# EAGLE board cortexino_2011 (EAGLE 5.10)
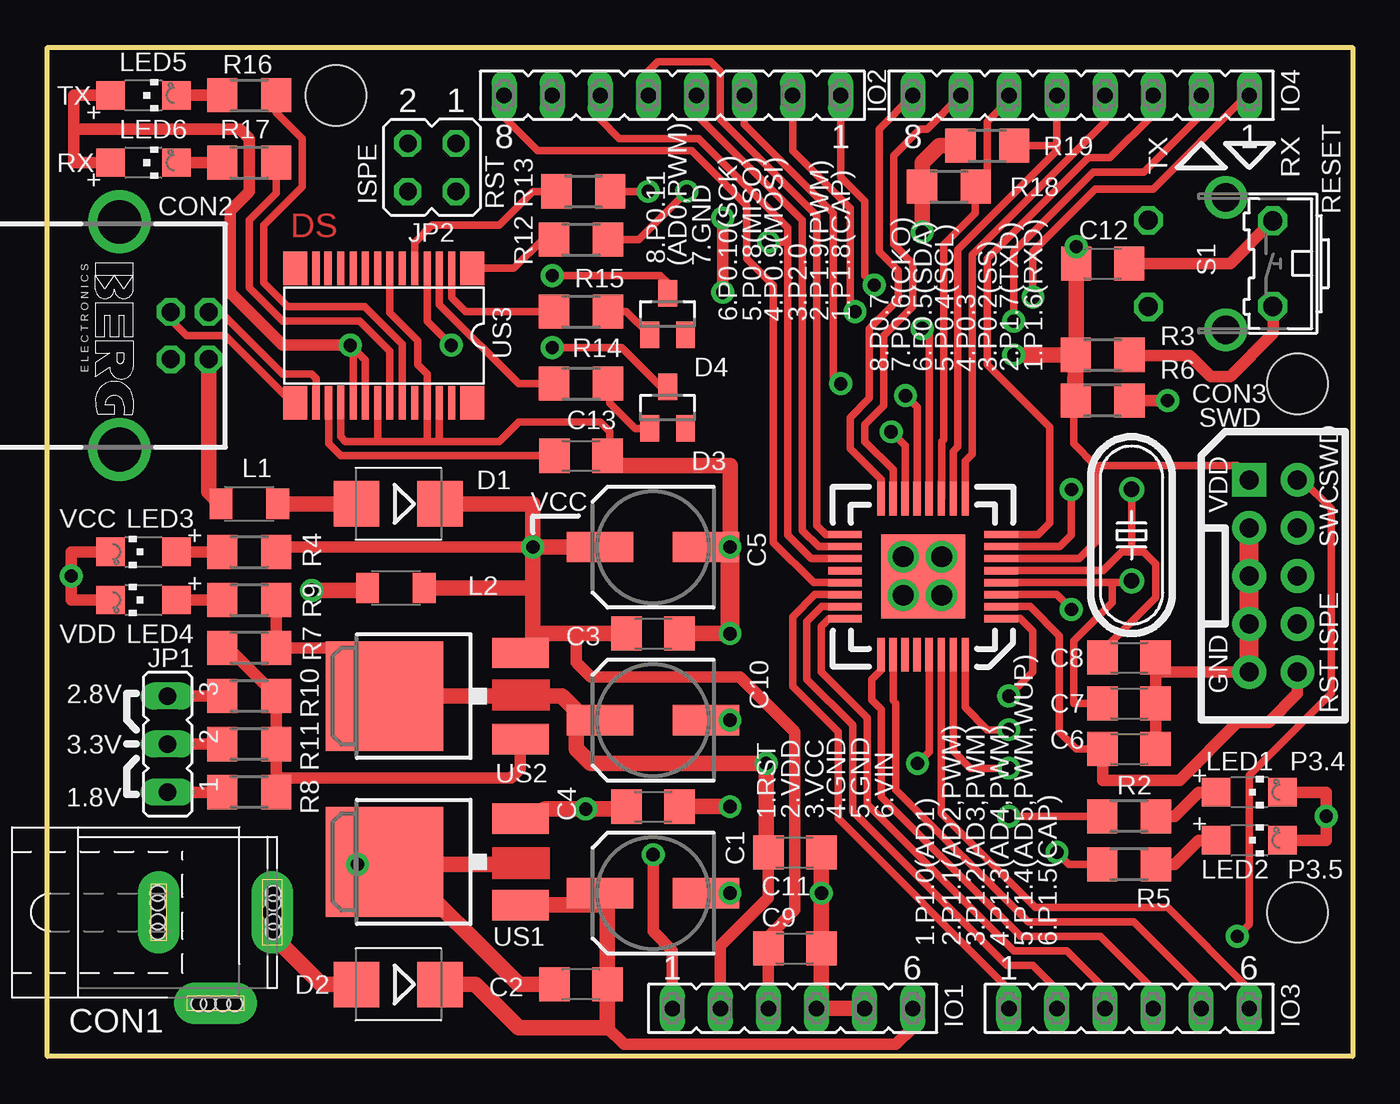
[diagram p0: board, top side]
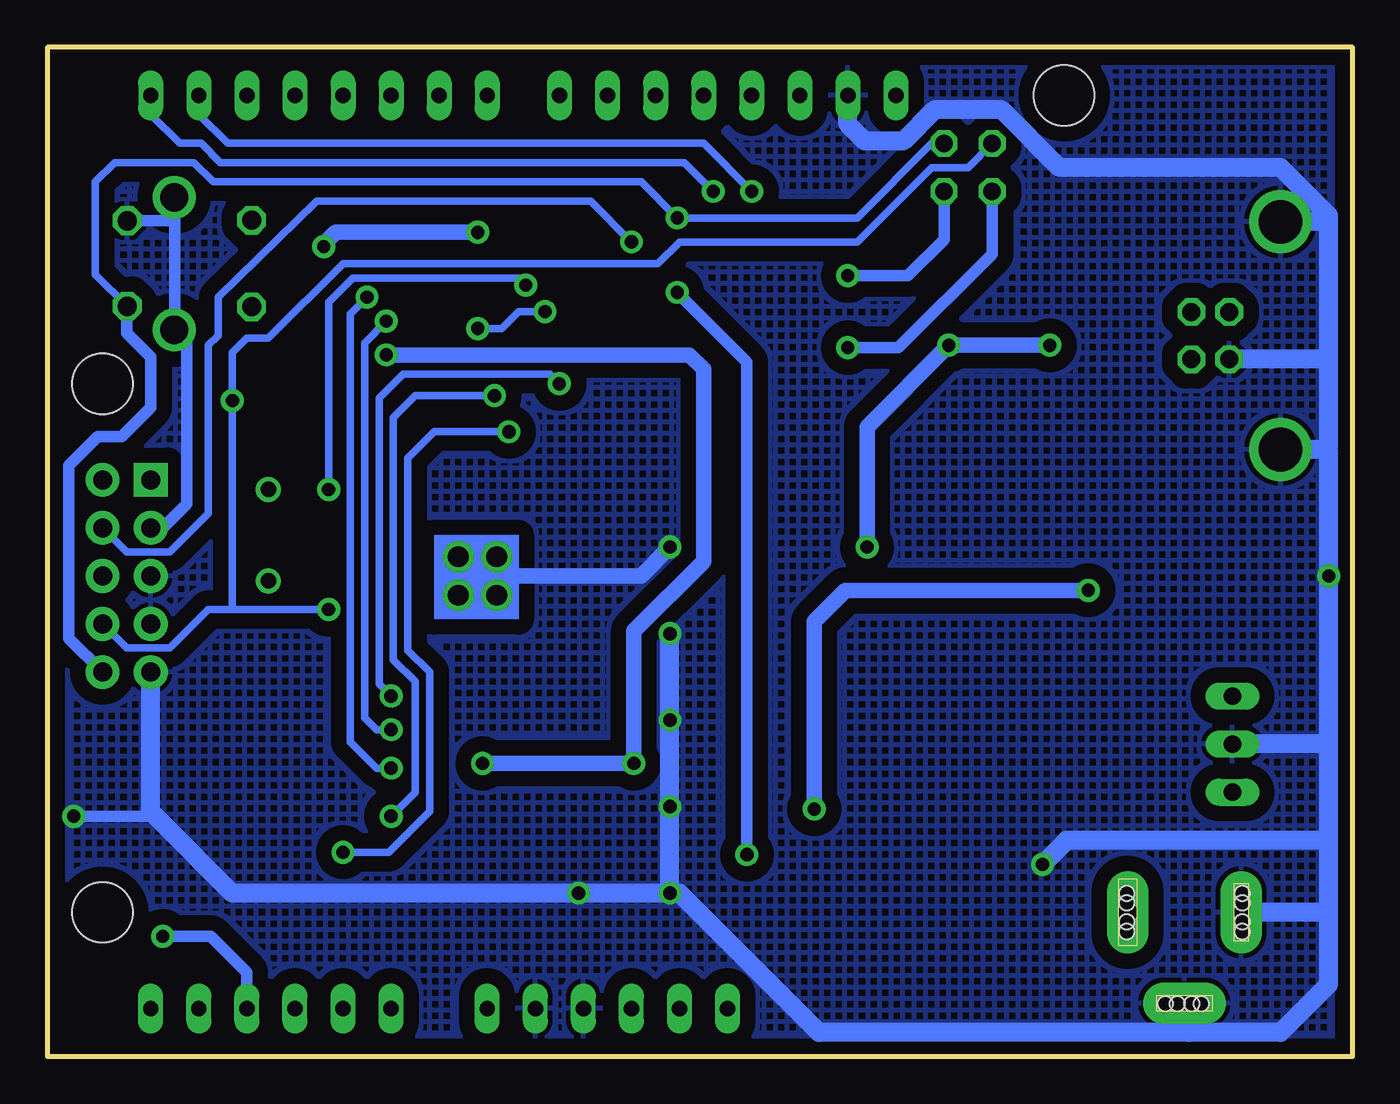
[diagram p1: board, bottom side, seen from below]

Size 68.96 x 53.34 mm. Coordinates in mm from the lower left corner, seen from the top.
Outline: 0,53.34 68.96,53.34 68.96,0 0,0 0,53.34
Copper layers (1*16): Top 0.035mm / dielectric 1.5mm / Bottom 0.035mm
Design rules "default *": minimum track width 6mil, minimum drill 12mil, track to track 6mil, track to pad 6mil, pad to pad 6mil, via to via 6mil, smd to smd 6mil, copper to edge 30mil, drill to drill 6mil, minimum pad ring 10mil, minimum via ring 10mil, stop-mask expansion 4mil, vias tented up to drill 0mil, thermal gap 10mil
Net classes: 0 default: width 0.254 mm, drill 0.305 mm, clearance 0.152 mm; 1 power: width 0.61 mm, drill 0.508 mm, clearance 0.152 mm; 2 gnd: width 0.305 mm, drill 0.508 mm, clearance 0.152 mm; 3 usbvcc: width 0.508 mm, drill 0.508 mm, clearance 0.152 mm; 4 aref: width 0.406 mm
Holes 3.2 mm at 66.04,35.56 66.04,7.62 15.24,50.8
Holes 0.8 mm at 5.84,7.11 5.84,6.6 5.84,8.13 5.84,8.64 8.51,2.79 9.27,2.79 8,2.79 9.91,2.79 11.94,8.13 11.94,8.64 11.94,7.11 11.94,6.6

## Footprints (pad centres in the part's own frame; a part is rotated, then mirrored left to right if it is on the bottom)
SANYO-OSCON_SMD_C6 = smd 3.5 x 1.6: + 2.8,0; - -2.8,0
C1206 = smd 1.6 x 1.8: 1 -1.4,0; 2 1.4,0
SPC4077 = drill 0.8 pad 2.184 long: 1 -3,0; 2 0,-4.8 | drill 1 pad 2.184 long: 3 3,0
PN61729-S = drill 0.95 octagon: 1 1.25,4.71; 2 -1.25,4.71; 3 -1.25,2.71; 4 1.25,2.71 | drill 2.3 pad 2.9 round: S1 -6.02,0; S2 6.02,0
CON10 = drill 1 pad 1.778 square: 1 -1.27,5.08 | drill 1 pad 1.778 round: 2 1.27,5.08; 3 -1.27,2.54; 4 1.27,2.54; 5 -1.27,0; 6 1.27,0; 7 -1.27,-2.54; 8 1.27,-2.54; 9 -1.27,-5.08; 10 1.27,-5.08
SMB = smd 2.4 x 2.4: A 2.2,0; C -2.2,0
SOT23 = smd 1 x 1.4: 1 -0.95,-1.1; 2 0.95,-1.1; 3 0,1.1
FE06 = drill 0.813 long: 1 -6.35,0; 2 -3.81,0; 3 -1.27,0; 4 1.27,0; 5 3.81,0; 6 6.35,0
FE08 = drill 0.813 long: 1 -8.89,0; 2 -6.35,0; 3 -3.81,0; 4 -1.27,0; 5 1.27,0; 6 3.81,0; 7 6.35,0; 8 8.89,0
JP2 = drill 0.914 long: 1 -2.54,0; 2 0,0; 3 2.54,0
JP2Q = drill 0.914 octagon: 1 -1.27,-1.27; 2 -1.27,1.27; 3 1.27,-1.27; 4 1.27,1.27
L3216C = smd 1.2 x 1.6: 1 -1.5,0; 2 1.5,0
CHIPLED_1206 = smd 1.5 x 1.5: A 0,-1.75; C 0,1.75
HC49/S = drill 0.813 round: 1 -2.413,0; 2 2.413,0
R1206 = smd 1.6 x 1.803: 1 -1.422,0; 2 1.422,0
B3F-31XX = drill 1.016 octagon: 1 -2.261,-1.245; 2 2.261,-1.245 | drill 1.499 pad 2.159 round: 3 -3.505,1.245; 4 3.505,1.245
DPACK = smd 1.6 x 3: 1 -2.28,-4.8; 3 2.28,-4.8 | smd 5.8 x 6.2: 4 0,2.38
TSSOP28 = smd 1.27 x 1.778: 1 -4.674,-3.556; 14 4.674,-3.556; 15 4.674,3.556; 28 -4.674,3.556 | smd 0.381 x 1.778: 2 -3.581,-3.556; 3 -2.921,-3.556; 4 -2.286,-3.556; 5 -1.626,-3.556; 6 -0.965,-3.556; 7 -0.305,-3.556; 8 0.33,-3.556; 9 0.991,-3.556; 10 1.626,-3.556; 11 2.286,-3.556; 12 2.946,-3.556; 13 3.581,-3.556; 16 3.581,3.556; 17 2.921,3.556; 18 2.286,3.531; 19 1.626,3.556; 20 0.991,3.556; 21 0.33,3.556; 22 -0.305,3.556; 23 -0.965,3.556; 24 -1.626,3.556; 25 -2.286,3.556; 26 -2.921,3.556; 27 -3.581,3.556
HVQFN33 = smd 0.381 x 1.778: 1 -2.54,-3.81; 2 -1.905,-3.81; 3 -1.27,-3.81; 4 -0.635,-3.81; 5 0,-3.81; 6 0.635,-3.81; 7 1.27,-3.81; 8 1.905,-3.81; 17 1.905,4.445; 18 1.27,4.445; 19 0.635,4.445; 20 0,4.445; 21 -0.635,4.445; 22 -1.27,4.445; 23 -1.905,4.445; 24 -2.54,4.445 | smd 1.778 x 0.381: 9 3.81,-1.905; 10 3.81,-1.27; 11 3.81,-0.635; 12 3.81,0; 13 3.81,0.635; 14 3.81,1.27; 15 3.81,1.905; 16 3.81,2.54; 25 -4.445,2.54; 26 -4.445,1.905; 27 -4.445,1.27; 28 -4.445,0.635; 29 -4.445,0; 30 -4.445,-0.635; 31 -4.445,-1.27; 32 -4.445,-1.905 | smd 4.445 x 4.445: 33 -0.318,0.318

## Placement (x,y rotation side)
C1  100u  [SANYO-OSCON_SMD_C6]  32,8.64 180 top
C2  100n  [C1206]  28.19,3.81 180 top
C3  100u  [SANYO-OSCON_SMD_C6]  32,26.92 180 top
C4  100n  [C1206]  32,13.21 0 top
C5  100n  [C1206]  32,22.35 0 top
C6  100n  [C1206]  57.15,16.26 0 top
C7  18p  [C1206]  57.15,18.67 0 top
C8  18p  [C1206]  57.15,21.08 0 top
C9  100n  [C1206]  39.5,5.71 0 top
C10  100u  [SANYO-OSCON_SMD_C6]  32,17.78 180 top
C11  100n  [C1206]  39.5,10.79 0 top
C12  100n  [C1206]  55.75,41.91 0 top
C13  100n  [C1206]  28.19,31.75 0 top
CON1  [SPC4077]  8.89,7.62 0 top
CON2  [PN61729-S]  3.81,38.1 270 top
CON3  [CON10]  64.77,25.4 0 top
D1  BAS85  [SMB]  18.54,29.21 180 top
D2  4007  [SMB]  18.54,3.81 180 top
D3  [SOT23]  32.77,34.29 0 top
D4  [SOT23]  32.77,39.24 0 top
IO1  [FE06]  39.37,2.54 0 top
IO2  [FE08]  33.02,50.8 180 top
IO3  [FE06]  57.15,2.54 0 top
IO4  [FE08]  54.61,50.8 180 top
JP1  [JP2]  6.35,16.51 90 top
JP2  [JP2Q]  20.32,46.99 180 top
L1  1uH  [L3216C]  10.67,29.21 0 top
L2  1uH  [L3216C]  18.41,24.77 0 top
LED1  [CHIPLED_1206]  63.5,13.97 270 top
LED2  [CHIPLED_1206]  63.5,11.43 270 top
LED3  [CHIPLED_1206]  5.08,26.67 90 top
LED4  [CHIPLED_1206]  5.08,24.13 90 top
LED5  [CHIPLED_1206]  5.08,50.8 270 top
LED6  [CHIPLED_1206]  5.08,47.24 270 top
Q1  12MHz  [HC49/S]  57.28,27.56 270 top
R2  1k  [R1206]  57.15,12.7 0 top
R3  10k  [R1206]  55.75,37.08 180 top
R4  1k  [R1206]  10.67,26.67 180 top
R5  1k  [R1206]  57.15,10.16 0 top
R6  10k  [R1206]  55.75,34.67 0 top
R7  330R  [R1206]  10.67,21.59 0 top
R8  10R  [R1206]  10.67,13.97 0 top
R9  1k  [R1206]  10.67,24.13 180 top
R10  220R  [R1206]  10.67,19.05 0 top
R11  150R  [R1206]  10.67,16.51 0 top
R12  1k  [R1206]  28.19,43.18 180 top
R13  1k  [R1206]  28.32,45.72 180 top
R14  1k  [R1206]  28.19,35.56 180 top
R15  1k  [R1206]  28.19,39.37 180 top
R16  1k  [R1206]  10.67,50.8 180 top
R17  1k  [R1206]  10.67,47.24 180 top
R18  4k7  [R1206]  47.62,45.97 180 top
R19  4k7  [R1206]  49.66,48.13 180 top
S1  [B3F-31XX]  63.5,41.91 90 top
US1  78M05  [DPACK]  20.19,10.29 90 top
US2  1117-1.8  [DPACK]  20.19,19.05 90 top
US3  [TSSOP28]  17.78,38.1 180 top
US4  LPC1114  [HVQFN33]  46.58,25.68 90 top

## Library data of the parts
C1-C13 L1 L2 R2-R19 = rcl
CON1 = con-jack
CON2 = con-berg
CON3 US4 = LPC1114
D1-D4 = diode
IO1-IO4 = con-lsta
JP1 JP2 = jumper
LED1-LED6 = led
Q1 = crystal
S1 = switch-omron
US1 US2 = v-reg
US3 = DS

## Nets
AREF: IO2.8 US4.21
GND [gnd]: C1.- C2.2 C3.- C4.2 C5.2 C6.2 C7.2 C8.2 C9.2 C10.- C11.2 C12.2 C13.2 CON1.1 CON1.2 CON2.4 CON2.S1 CON2.S2 CON3.3 CON3.5 CON3.7 CON3.9 IO1.4 IO1.5 IO2.7 JP1.2 LED1.C LED2.C LED3.C LED4.C R11.1 S1.2 US1.4 US3.7 US3.18 US3.21 US3.25 US3.26 US4.33
ISPE: CON3.8 JP2.3 R6.2 US4.3
LED1: R2.1 US4.13
LED2: R5.1 US4.14
MISO: IO2.5 US4.17
MOSI: IO2.4 US4.18
N$1: CON1.3 D2.A
N$3: R14.2 US3.3
N$4: LED1.A R2.2
N$5: LED2.A R5.2
N$7: D4.1 R15.1
N$8: JP1.3 R10.1
N$9: C4.1 L2.1 US1.3
N$10: JP1.1 R8.1
N$11: D1.A L1.2
N$12: LED4.A R9.2
N$15: LED3.A R4.2
N$16: CON2.2 US3.16
N$17: CON2.3 US3.15
N$18: R7.1 R8.2 R10.2 R11.2 US2.1
N$19: D3.1 R14.1
N$20: C13.1 US3.17
N$21: R15.2 US3.2
N$24: D3.3 JP2.4
N$25: D4.3 JP2.2
N$28: R12.2 US3.1
N$29: R13.2 US3.5
N$31: R16.1 US3.23
N$32: R17.1 US3.22
N$33: LED5.C R16.2
N$34: LED6.C R17.2
P0_2: IO4.3 US4.8
P0_3: IO4.4 US4.9
P0_4: IO4.5 R19.1 US4.10
P0_5: IO4.6 R18.1 US4.11
P0_6: IO4.7 US4.15
P0_7: IO4.8 US4.16
P1_0: IO3.1 US4.22
P1_1: IO3.2 US4.23
P1_2: IO3.3 US4.24
P1_3: CON3.2 IO3.4 US4.25
P1_4: IO3.5 US4.26
P1_5: IO3.6 US4.30
P1_8: IO2.1 US4.7
P1_9: IO2.2 US4.12
RST: C6.1 CON3.10 IO1.1 JP2.1 R3.1 S1.1 US4.2
RXD: IO4.1 R12.1 US4.31
SCK: CON3.4 IO2.6 US4.19
SS: IO2.3 US4.1
TXD: IO4.2 R13.1 US4.32
VCC: C3.+ C5.1 C9.1 D1.C IO1.3 L2.2 LED5.A LED6.A R4.1 US2.3 US3.4 US3.19 US3.20
VDD: C10.+ C11.1 C12.1 CON3.1 IO1.2 R3.2 R6.1 R7.2 R9.1 R18.2 R19.2 US2.4 US4.6 US4.29
VIN: C1.+ C2.1 D2.C IO1.6 US1.1
VUSB: CON2.1 L1.1
XIN: C7.1 Q1.2 US4.4
XOUT: C8.1 Q1.1 US4.5

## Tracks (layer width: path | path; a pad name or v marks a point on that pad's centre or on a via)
AREF
  Top 0.406: US4.21 40.49,25.04 38.35,27.18 38.35,40.77 36.96,42.16 36.96,44.96 34.04,47.88 25.91,47.88 24.13,49.66 IO2.8
GND  (via drill 0.7, 1.1)
  Top 0.406: US3.18 15.49,32.77 15.75,32.51 17.53,32.51 | 20.07,32.51 17.53,32.51 | 20.07,32.51 US3.25 20.07,36.07 19.56,36.58 19.56,37.85 18.09,39.32 US3.7 | US3.21 17.45,32.59 17.53,32.51 | 20.83,32.51 20.07,32.51 | US3.26 20.7,32.64 20.83,32.51 | 20.83,32.51 23.88,32.51 24.89,33.53 29.21,33.53 29.72,33.02 29.72,31.87 C13.2 | 46.23,25.53 46.23,25.4 v47.24,24.38
  Top 0.61: LED3.C 1.27,26.67 v1.27,25.4 1.27,24.13 LED4.C | JP1.2 R11.1 | v36.07,8.64 C1.- | C12.2 62.49,41.91 S1.2 | C6.2 C7.2 58.55,20.32 | CON3.9 58.55,20.32 | C8.2 58.55,20.32 | LED1.C 67.56,13.97 v67.56,12.7 67.56,11.43 LED2.C
  Top 0.813: C13.2 29.59,31.62 29.97,31.24 36.07,31.24 v36.07,26.92 C3.- | v36.07,13.21 C4.2 | v36.07,17.78 C10.- | v36.07,22.35 C5.2 | IO1.5 IO1.4 40.9,2.8 C9.2 v40.9,8.63 v40.89,8.64 v40.9,8.64 C11.2 | 46.23,25.4 US4.33 | US1.4 18.41,10.29 24.89,3.81 C2.2
  Top 1.016: v36.07,22.35 v36.07,26.92 | CON3.9 CON3.7 CON3.5 CON3.3 | v16.38,10.16 17.69,10.16 US1.4
  Bottom 0.406: v45.21,26.42 v47.24,26.42 v47.24,24.38 v45.21,24.38 45.21,25.4 v45.21,26.42
  Bottom 0.61: S1.2 62.26,44.17 62.23,44.2 | 62.23,44.2 62.23,45.47 | CON3.3 62.87,27.94 61.59,29.21 61.59,37.72 62.23,38.35 62.23,44.2 | 1.27,22.1 1.4,21.97 | v67.56,12.7 63.25,12.7 62.99,12.45
  Bottom 0.813: 45.21,25.4 37.59,25.4 v36.07,26.92
  Bottom 1.016: 1.27,32.26 1.27,36.83 | CON2.4 1.29,36.85 1.27,36.83 | 1.27,11.43 1.27,16.26 | 1.27,16.26 1.27,22.1 1.27,32 1.35,32.08 CON2.S2 | 8.64,1.27 3.81,1.27 1.27,3.81 1.27,7.49 | CON1.2 8.89,1.52 8.64,1.27 | 1.27,36.83 1.27,43.94 | 1.27,43.94 1.27,44.45 3.81,46.99 15.49,46.99 18.54,50.04 22.1,50.04 23.75,48.39 25.78,48.39 26.67,49.28 IO2.7 | CON2.S1 1.45,44.12 1.27,43.94 | JP1.2 1.52,16.51 1.27,16.26 | v36.07,8.64 v36.07,13.21 v36.07,17.78 v36.07,22.35 | v36.07,8.64 v40.89,8.64 59.18,8.64 62.99,12.45 63.5,12.95 CON3.9 | 8.64,1.27 28.19,1.27 35.56,8.64 v36.07,8.64 | 1.27,7.49 1.27,11.43 | 1.27,11.43 15.11,11.43 v16.38,10.16 | CON1.1 1.4,7.62 1.27,7.49
  pour Bottom (isolate 0.813, hatched): 0,53.34 68.96,53.34 68.96,0 0,0
ISPE  (via drill 0.7)
  Top 0.406: US4.3 53.31,24.41 v54.1,23.62
  Top 0.61: v59.18,34.67 R6.2
  Bottom 0.406: 59.18,23.62 v54.1,23.62 | JP2.3 20.32,46.99 22.23,46.99 26.16,43.05 35.56,43.05 36.7,41.91 53.34,41.91 57.28,37.97 58.42,37.97 59.18,37.21 v59.18,34.67 59.18,23.62 | CON3.8 64.77,21.59 62.48,21.59 60.45,23.62 59.18,23.62
LED1  (via drill 0.7)
  Top 0.406: v50.8,12.7 R2.1 | US4.13 45.95,34.31 v45.34,34.92
  Bottom 0.406: v45.34,34.92 49.53,34.92 50.67,33.78 50.67,20.95 49.53,19.81 49.53,13.97 v50.8,12.7
LED2  (via drill 0.7)
  Top 0.406: v53.34,10.79 53.95,10.16 R5.1 | US4.14 45.31,32.28 v44.58,33.02
  Bottom 0.406: v44.58,33.02 48.51,33.02 49.91,31.62 49.91,21.46 48.77,20.32 48.77,12.95 50.93,10.79 v53.34,10.79
MISO
  Top 0.406: US4.17 41.12,27.58 40.64,28.07 40.64,44.45 35.56,49.53 35.56,52.07 35.05,52.58 32.26,52.58 31.75,52.07 IO2.5
MOSI
  Top 0.406: US4.18 40.74,26.95 39.88,27.81 39.88,44.2 34.29,49.78 IO2.4
N$1
  Top 0.813: CON1.3 11.89,6.4 14.48,3.81 D2.A
N$2
  Top 0.813: 20.07,10.16 24.77,10.16
N$3
  Top 0.406: US3.3 20.7,39.75 24.89,35.56 R14.2
N$4
  Top 0.61: R2.2 59.56,12.7 60.83,13.97 LED1.A
N$5
  Top 0.61: R5.2 59.56,10.16 60.83,11.43 LED2.A
N$7
  Top 0.406: R15.1 30.59,39.37 D4.1
N$8
  Top 0.61: JP1.3 R10.1
N$9  (via drill 0.7)
  Top 0.813: C4.1 30.48,13.08 v28.45,13.08 26.29,13.08 25.77,12.57 US1.3 | v13.97,24.64 16.79,24.64 L2.1
  Bottom 0.813: v13.97,24.64 26.8,24.64 28.45,22.99 v28.45,13.08
N$10
  Top 0.61: JP1.1 R8.1
N$11
  Top 0.813: L1.2 D1.A
N$12
  Top 0.61: LED4.A R9.2
N$13  (via drill 1)
  other vias: 58.17,44.2
N$14  (via drill 1)
  other vias: 58.17,39.62
N$15
  Top 0.61: LED3.A R4.2
N$16
  Top 0.406: CON2.2 9.16,39.35 12.45,36.07 13.97,36.07 14.2,35.84 US3.16
N$17
  Top 0.406: CON2.3 6.52,38.95 7.37,38.1 9.4,38.1 12.95,34.54 US3.15
N$18
  Top 0.61: R8.2 12.09,14.61 | 12.09,14.61 R11.2 R10.2 9.55,21.59 R7.1 | US2.1 24.99,15.21 24.51,14.73 12.22,14.73 12.09,14.61
N$19
  Top 0.406: R14.1 29.72,35.46 29.72,34.54 31.07,33.19 D3.1
N$20
  Top 0.406: US3.17 14.86,32.38 15.49,31.75 C13.1
N$21
  Top 0.406: US3.2 21.36,40.11 22.1,39.37 R15.2
N$24  (via drill 0.7)
  Top 0.406: v26.67,37.47 30.35,37.47 32.38,35.43 32.68,35.39 D3.3
  Bottom 0.61: v26.67,37.47 24,37.47 19.05,42.42 JP2.4
N$25  (via drill 0.7)
  Top 0.406: v26.67,41.27 32.38,41.27 32.77,40.89 32.68,40.47 32.77,40.39 D4.3
  Bottom 0.61: v26.67,41.27 23.5,41.27 21.59,43.18 JP2.2
N$28
  Top 0.406: US3.1 24.64,41.66 26.16,43.18 R12.2
N$29
  Top 0.406: R13.2 25.65,45.72 23.88,43.94 20.32,43.94 19.41,43.03 US3.5
N$31
  Top 0.406: US3.23 18.75,37.64 16.76,39.62 12.7,39.62 11.43,40.89 11.43,43.94 13.46,45.97 13.46,48.51 12.09,49.89 R16.1
N$32
  Top 0.406: US3.22 18.09,37.29 16.51,38.86 12.45,38.86 10.67,40.64 10.67,44.2 12.09,45.62 R17.1
N$33
  Top 0.61: LED5.C R16.2
N$34
  Top 0.61: LED6.C R17.2
P0_2
  Top 0.406: US4.8 52.35,27.58 52.96,28.19 52.96,33.27 49.66,36.58 49.66,42.16 54.99,47.5 56.13,47.5 58.42,49.78 IO4.3
P0_3
  Top 0.406: US4.9 48.49,31.47 48.87,31.85 48.87,42.39 55.88,49.4 IO4.4
P0_4
  Top 0.406: US4.10 47.85,31.98 48.11,32.23 48.11,42.65 53.34,47.88 53.34,48.26 | 53.34,48.26 IO4.5 | R19.1 53.21,48.13 53.34,48.26
P0_5
  Top 0.406: US4.11 47.24,29.52 47.24,32.51 47.35,32.61 47.35,42.9 49.02,44.58 49.02,45.95 R18.1 49.66,46.58 49.66,49.4 50.8,50.55 IO4.6
P0_6
  Top 0.406: US4.15 44.68,31.01 43.18,32.51 43.18,33.4 44.2,34.42 44.2,38.1 45.72,39.62 45.72,41.91 44.7,42.93 44.7,47.62 46.1,49.02 46.48,49.02 IO4.7
P0_7
  Top 0.406: US4.16 44.04,30.5 42.42,32.13 42.42,33.78 43.43,34.8 43.43,38.48 44.96,40.01 44.96,41.53 43.94,42.55 43.94,49.02 IO4.8
P1_0
  Top 0.406: IO3.1 50.8,3.56 41.78,12.57 41.78,17.14 39.37,19.56 39.37,23.24 40.54,24.41 US4.22
P1_1
  Top 0.406: US4.23 40.92,23.77 40.13,22.99 40.13,19.94 42.55,17.53 42.55,12.95 50.67,4.83 52.07,4.83 53.34,3.56 IO3.2
P1_2
  Top 0.406: US4.24 41.3,23.14 40.89,22.73 40.89,20.32 43.31,17.91 43.31,13.34 51.05,5.59 53.85,5.59 55.88,3.56 IO3.3
P1_3  (via drill 0.7)
  Top 0.406: IO3.4 58.42,3.56 55.63,6.35 51.44,6.35 44.07,13.72 44.07,18.34 43.56,18.85 43.56,19.94 44.04,20.42 US4.25 | CON3.2 66.29,30.48 67.82,28.96 67.82,19.18 63.5,14.86 63.5,6.99 v62.87,6.35
  Bottom 0.61: v62.87,6.35 60.33,6.35 58.42,4.45 IO3.4
P1_4
  Top 0.406: US4.26 44.68,18.82 44.83,18.67 44.83,14.1 51.82,7.11 53.09,7.11 57.4,7.11 60.96,3.56 IO3.5
P1_5
  Top 0.406: US4.30 47.22,12.85 52.2,7.87 59.18,7.87 63.5,3.56 IO3.6
P1_8  (via drill 0.7)
  Top 0.406: US4.7 53.49,26.95 54.1,27.56 v54.1,29.97 | IO2.1 41.91,46.48 43.18,45.21 43.18,41.27 v43.69,40.77
  Bottom 0.406: v54.1,29.97 54.1,39.88 52.83,41.15 44.07,41.15 v43.69,40.77
P1_9  (via drill 0.7)
  Top 0.406: IO2.2 39.37,47.88 42.42,44.83 42.42,39.62 v42.67,39.37 | US4.12 46.58,38.12 v46.23,38.48
  Bottom 0.406: v46.23,38.48 44.96,38.48 44.07,39.37 v42.67,39.37
RST  (via drill 0.7)
  Top 0.406: US4.2 51.92,23.77 53.47,22.23 53.47,17.14 54.36,16.26 C6.1
  Top 0.61: v35.69,40.39 v35.69,44.32 | CON3.10 66.04,19.18 64.52,17.65 62.87,17.65 59.82,14.61 55.75,14.61 55.75,16.64 55.63,16.76 55.63,16.38 C6.1 | v32,10.67 32,6.6 33.02,5.59 IO1.1 | S1.1 64.77,39.62 64.77,38.23 62.48,35.94 61.47,35.94 60.35,37.06 57.2,37.06 R3.1
  Bottom 0.406: JP2.1 22.23,48.26 26.16,44.32 v35.69,44.32 37.59,46.23 60.2,46.23 61.21,47.24 65.41,47.24 66.42,46.23 66.42,41.33 S1.1
  Bottom 0.61: CON3.10 67.82,22.1 67.82,31.24 66.29,32.77 65.02,32.77 63.5,34.29 63.5,36.96 64.77,38.23 64.77,39.62 S1.1 | v32,10.67 32,36.7 v35.69,40.39
RXD  (via drill 0.7)
  Top 0.406: R12.1 31.24,43.18 v33.78,45.72 | US4.31 47.85,16.15 48.77,15.24 v50.8,15.24 | IO4.1 63.37,50.8 58.42,45.85 55.37,45.85 52.07,42.55 v52.07,40.13
  Bottom 0.406: v50.8,15.24 51.56,15.24 52.96,16.64 52.96,39.24 v52.07,40.13 | v33.78,45.72 35.31,47.24 59.82,47.24 60.83,48.26 61.98,48.26 63.5,49.78 IO4.1
SCK  (via drill 0.7)
  Top 0.406: US4.19 40.36,26.31 39.12,27.56 39.12,43.05 | 39.12,43.05 39.12,43.81 34.42,48.51 30.23,48.51 29.21,49.53 IO2.6 | 39.12,43.05 v38.1,43.05
  Bottom 0.406: CON3.4 64.77,26.67 62.48,26.67 60.45,28.7 60.45,37.59 59.94,38.1 59.94,40.13 54.74,45.21 40.26,45.21 v38.1,43.05
SS  (via drill 0.7)
  Top 0.406: US4.1 51.41,23.14 52.07,22.48 52.07,20.32 v50.8,19.05 | IO2.3 36.83,49.28 41.53,44.58 41.53,35.94 v41.91,35.56
  Bottom 0.406: v50.8,19.05 51.44,19.68 51.44,34.8 50.16,36.07 42.42,36.07 v41.91,35.56
TXD  (via drill 0.7)
  Top 0.406: v31.75,45.72 R13.1 | US4.32 48.49,18.44 49.66,17.27 v50.8,17.27 | v51.05,38.86 51.05,42.55 55.24,46.74 57.91,46.74 60.96,49.78 IO4.2
  Bottom 0.406: v50.8,17.27 51.56,17.27 52.2,17.91 52.2,37.72 v51.05,38.86 | v31.75,45.72 34.29,48.26 59.44,48.26 60.96,49.78 IO4.2
VCC  (via drill 0.7)
  Top 0.406: US3.20 16.79,36.8 v16,37.59 16.15,37.49 US3.19 | US3.4 20.07,38.86 v21.34,37.59
  Top 0.61: 1.4,49.02 1.4,50.8 LED5.A | 1.4,49.02 10.16,49.02 10.67,48.51 10.67,45.72 9.65,44.7 9.65,40.39 12.45,37.59 v16,37.59 | LED6.A 3.3,47.24 1.4,47.24 1.4,49.02 | R4.1 12.45,26.67 12.45,26.92 v25.65,26.92 | 27.94,22.35 27.94,20.83 28.7,20.07 36.58,20.07 39.5,17.14 39.5,7.75 38.1,6.35 C9.1 IO1.3
  Top 0.813: D1.C 25.65,29.21 v25.65,26.92 | v25.65,26.92 25.65,24.64 | 25.65,24.64 25.65,22.35 | v25.65,26.92 C3.+ | 25.65,22.35 27.94,22.35 C5.1 | 25.65,22.35 25.65,21.61 US2.3 | L2.2 25.53,24.77 25.65,24.64
  Bottom 0.813: v16,37.59 v21.34,37.59 25.65,33.27 v25.65,26.92
VDD  (via drill 0.7)
  Top 0.406: US4.29 46.58,16.1 v45.97,15.49 | US4.6 54.51,26.31 55.5,27.3 55.5,31.24 | CON3.1 62.87,31.24 55.5,31.24 | 55.5,31.24 55.37,31.24 54.23,32.38 54.23,34.57 R6.1
  Top 0.61: R9.1 R7.2 15.65,21.59 US2.4 | C11.1 38.1,8.38 35.56,5.84 IO1.2
  Top 0.813: 28.45,17.78 27.94,17.78 27.94,16.26 28.7,15.49 v37.97,15.49 | 28.45,17.78 C10.+ | v37.97,15.49 37.08,15.49 | US2.4 27.18,19.05 28.45,17.78 | v37.97,15.49 37.97,11.17 C11.1 | v51.05,37.08 54.36,37.08 | 54.36,37.08 54.23,34.77 R6.1 | 54.36,37.08 54.33,35.66 R3.2 54.35,37.11 C12.1 v54.35,42.8 v54.36,42.8 | v46.23,43.56 46.23,45.95 R18.2 46.23,46 46.23,47.24 47.12,48.13 R19.2
  Bottom 0.813: v51.05,37.08 35.05,37.08 34.29,36.32 34.29,26.16 37.97,22.48 v37.97,15.49 v45.97,15.49 | v54.36,42.8 54.36,42.93 53.72,43.56 v46.23,43.56
VIN
  Top 0.61: IO1.6 45.72,1.52 44.83,0.64 30.48,0.64 29.59,1.52
  Top 0.813: D2.C 22.61,3.81 24.89,1.52 29.59,1.52 C2.1 29.59,7.87 | 29.59,7.87 29.59,8.51 29.46,8.64 C1.+ | US1.1 29.46,8.01 29.59,7.87
VUSB
  Top 0.813: CON2.1 8.52,29.86 L1.1
XIN
  Top 0.406: C7.1 54.23,18.67 54.23,21.97 56.26,24 56.26,25.04 | US4.4 56.26,25.04 | 56.26,25.04 57.17,25.04 Q1.2
XOUT
  Top 0.406: US4.5 55.78,25.68 56.77,26.67 57.15,26.67 | 57.15,26.67 57.91,26.67 58.55,26.04 58.55,24.26 55.63,21.34 55.63,21.21 C8.1 | Q1.1 57.28,26.8 57.15,26.67
(copper drawn outside any net)
  shapes: Bottom area x1, Top area x2

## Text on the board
Top: DS
tPlace: TX | + | RESET | ISPE | RST | RX | + | 8.P0.11 | (AD0,PWM) | 7.GND | 6.P0.10(SCK) | 5.P0.8(MISO) | 4.P0.9(MOSI) | 3.P2.0 | 2.P1.9(PWM) | 1.P1.8(CAP) | 8.P0.7 | 7.P0.6(CKO) | 6.P0.5(SDA) | 5.P0.4(SCL) | 4.P0.3 | 3.P0.2(SS) | 2.P1.7(TXD) | 1.P1.6(RXD) | SWD | VDD | SWD | VCC | VCC | + | SWC | + | VDD | ISPE | 2.8V | GND | RST | 3.3V | P3.4 | 1.8V | + | 1.RST | 2.VDD | 3.VCC | 4.GND | 5.GND | 6.VIN | + | P3.5 | 1.P1.0(AD1) | 2.P1.1(AD2,PWM) | 3.P1.2(AD3,PWM) | 4.P1.3(AD4,PWM) | 5.P1.4(AD5,PWM,WUP) | 6.P1.5(CAP) | D2
tNames: RX | TX
Reference: C8 | R7 | R5 | R6 | R4 | C3 | C2 | R9 | R8 | R1 | R2 | C1 | C4 | C5 | X2 | C7 | C6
